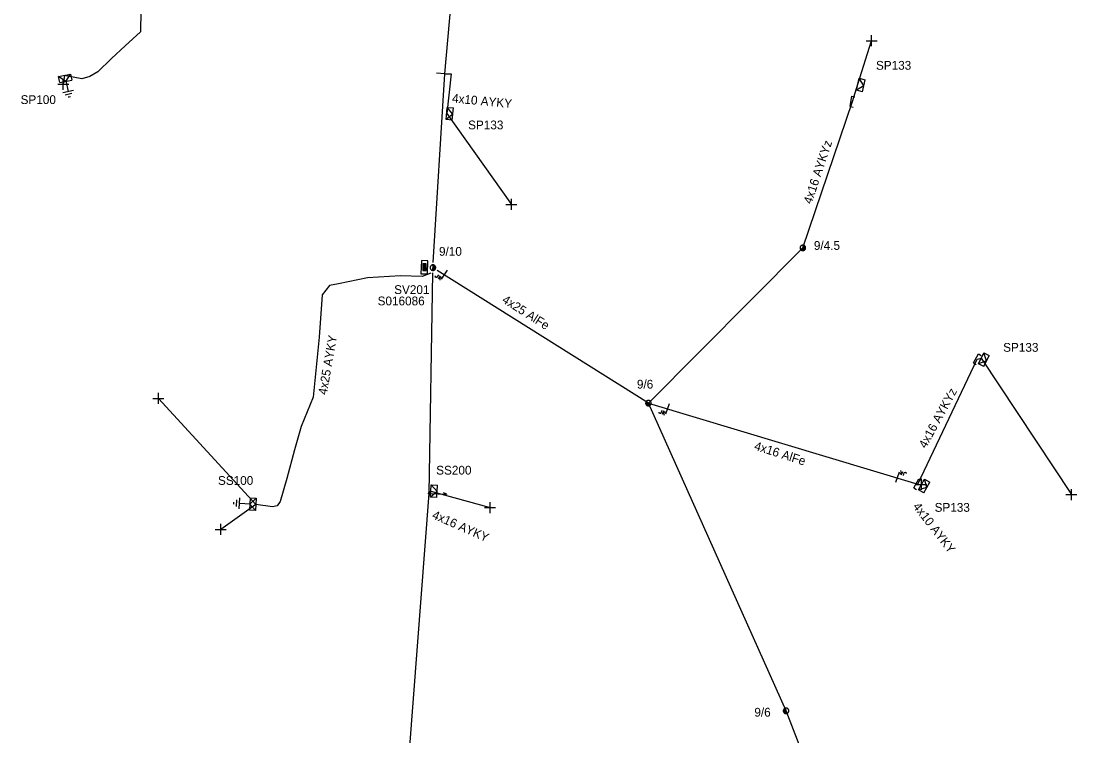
# Model space of a CAD drawing. Extents: x -717562 to -713845, y -1151196 to -1143903.
# Drawn here: x -717014.4 to -716894.3, y -1144985.4 to -1144904.2 of the extents above; entities that cross this region are included whole.
import ezdxf

# ---------------------------------------------------------------- set-up
doc = ezdxf.new("R2010")
doc.units = 0
for name, color, linetype in [('Vrstva 1', 7, 'Continuous'), ('Vrstva 12', 7, 'Continuous'), ('Vrstva 13', 7, 'Continuous'), ('Vrstva 14', 7, 'Continuous'), ('Vrstva 15', 7, 'Continuous'), ('Vrstva 18', 7, 'Continuous'), ('Vrstva 2', 7, 'Continuous'), ('Vrstva 28', 7, 'Continuous'), ('Vrstva 29', 7, 'Continuous'), ('Vrstva 30', 7, 'Continuous'), ('Vrstva 31', 7, 'Continuous'), ('Vrstva 33', 7, 'Continuous'), ('Vrstva 34', 7, 'Continuous'), ('Vrstva 52', 7, 'Continuous'), ('Vrstva 54', 7, 'Continuous'), ('Vrstva 55', 7, 'Continuous'), ('Vrstva 59', 7, 'Continuous'), ('Vrstva 8', 7, 'Continuous'), ('Vrstva 9', 7, 'Continuous')]:
    doc.layers.add(name, color=color, linetype=linetype)

# ---------------------------------------------------------------- blocks, each defined once
blk = doc.blocks.new('NN440')
at = {"layer": 'Vrstva 2'}
for points in [[(0.63, 0), (0.63, 0.06), (0.62, 0.13), (0.6, 0.19), (0.58, 0.25), (0.55, 0.31), (0.51, 0.37), (0.47, 0.42), (0.42, 0.46), (0.37, 0.51), (0.32, 0.54), (0.26, 0.57), (0.2, 0.59), (0.13, 0.61), (0.07, 0.62), (0, 0.63), (-0.06, 0.62), (-0.13, 0.61), (-0.19, 0.59), (-0.26, 0.57), (-0.31, 0.54), (-0.37, 0.51), (-0.42, 0.46), (-0.47, 0.42), (-0.51, 0.37), (-0.54, 0.31), (-0.57, 0.25), (-0.6, 0.19), (-0.62, 0.13), (-0.63, 0.06), (-0.63, 0), (-0.63, -0.07), (-0.62, -0.14), (-0.6, -0.2), (-0.57, -0.26), (-0.54, -0.32), (-0.51, -0.37), (-0.47, -0.43), (-0.42, -0.47), (-0.37, -0.51), (-0.31, -0.55), (-0.26, -0.58), (-0.19, -0.6), (-0.13, -0.62), (-0.06, -0.63), (0, -0.63), (0.07, -0.63), (0.13, -0.62), (0.2, -0.6), (0.26, -0.58), (0.32, -0.55), (0.37, -0.51), (0.42, -0.47), (0.47, -0.43), (0.51, -0.37), (0.55, -0.32), (0.58, -0.26), (0.6, -0.2), (0.62, -0.14), (0.63, -0.07), (0.63, 0)], [(-0.63, 0), (0.63, 0)], [(-0.6, -0.18), (0.57, -0.18)], [(-0.51, -0.32), (0.5, -0.32)], [(-0.37, -0.47), (0.35, -0.47)]]:
    blk.add_lwpolyline(points, dxfattribs=at)
blk = doc.blocks.new('NN560')
at = {"layer": 'Vrstva 2'}
for points in [[(2, 0), (1.59, 0.14)], [(0, 0), (2, 0)], [(2, 0), (1.59, -0.13)]]:
    blk.add_lwpolyline(points, dxfattribs=at)
blk = doc.blocks.new('NN840')
at = {"layer": 'Vrstva 15'}
for points in [[(0, 0.62), (0, -0.63)], [(-0.75, -0.71), (-0.75, -0.66)], [(-0.73, -0.76), (-0.75, -0.71)], [(-0.66, -0.8), (-0.73, -0.76)], [(-0.63, -0.8), (-0.66, -0.8)], [(-0.56, -0.76), (-0.63, -0.8)], [(-0.54, -0.71), (-0.56, -0.76)], [(-0.54, -0.38), (-0.54, -0.71)], [(-0.33, -0.38), (-0.33, -0.8)], [(-0.33, -0.64), (-0.13, -0.38)], [(-0.26, -0.56), (-0.09, -0.8)]]:
    blk.add_lwpolyline(points, dxfattribs=at)
blk = doc.blocks.new('NN800')
at = {"layer": 'Vrstva 1'}
for points in [[(-0.44, 0.44), (0.44, -0.44)], [(-0.44, -0.44), (0.44, 0.44)]]:
    blk.add_lwpolyline(points, dxfattribs=at)
blk = doc.blocks.new('NN620')
at = {"layer": 'Vrstva 8'}
for points in [[(0.75, 0), (-0.75, 0)], [(-0.75, 0), (-0.75, -0.75)], [(0.75, -0.75), (0.75, 0)], [(-0.75, -0.75), (0.75, -0.75)], [(0.37, -0.18), (-0.38, -0.18)], [(-0.38, -0.18), (-0.38, -0.56)], [(-0.38, -0.56), (0.37, -0.56)], [(0.32, -0.23), (-0.33, -0.23)], [(-0.33, -0.23), (-0.33, -0.51)], [(-0.33, -0.51), (0.32, -0.51)], [(0.27, -0.27), (-0.28, -0.27)], [(-0.28, -0.27), (-0.28, -0.46)], [(-0.28, -0.46), (0.27, -0.46)], [(0.23, -0.32), (-0.23, -0.32)], [(-0.23, -0.32), (-0.23, -0.42)], [(-0.23, -0.42), (0.23, -0.42)], [(-0.19, -0.37), (0.19, -0.37)], [(0.23, -0.42), (0.23, -0.32)], [(0.27, -0.46), (0.27, -0.27)], [(0.32, -0.51), (0.32, -0.23)], [(0.37, -0.56), (0.37, -0.18)]]:
    blk.add_lwpolyline(points, dxfattribs=at)
blk = doc.blocks.new('NN630')
at = {"layer": 'Vrstva 9'}
for points in [[(0, -0.7), (-0.7, 0)], [(-0.7, -0.7), (-0.7, 0), (0.7, 0), (0.7, -0.7)], [(-0.7, -0.7), (0.7, -0.7)], [(0, -0.7), (0.7, 0)]]:
    blk.add_lwpolyline(points, dxfattribs=at)
blk = doc.blocks.new('NN810')
at = {"layer": 'Vrstva 14'}
for points in [[(0, -0.64), (0, -1.89)], [(0.63, -1.89), (-0.62, -1.89)], [(0.39, -2.2), (-0.4, -2.2)], [(0, -2.52), (-0.12, -2.52)], [(0.14, -2.52), (0, -2.52)]]:
    blk.add_lwpolyline(points, dxfattribs=at)
blk = doc.blocks.new('NN500')
at = {"layer": 'Vrstva 2'}
for points in [[(0, -0.24), (0.02, -0.23), (0.05, -0.23), (0.07, -0.22), (0.09, -0.22), (0.12, -0.2), (0.14, -0.19), (0.16, -0.18), (0.17, -0.16), (0.19, -0.14), (0.2, -0.12), (0.21, -0.1), (0.22, -0.07), (0.23, -0.05), (0.23, -0.02), (0.23, 0), (0.23, 0.02), (0.23, 0.05), (0.22, 0.07), (0.21, 0.1), (0.2, 0.12), (0.19, 0.14), (0.17, 0.16), (0.16, 0.17), (0.14, 0.19), (0.12, 0.2), (0.09, 0.21), (0.07, 0.22), (0.05, 0.23), (0.02, 0.23), (0, 0.23), (-0.03, 0.23), (-0.05, 0.23), (-0.07, 0.22), (-0.1, 0.21), (-0.12, 0.2), (-0.14, 0.19), (-0.16, 0.17), (-0.18, 0.16), (-0.19, 0.14), (-0.2, 0.12), (-0.22, 0.1), (-0.22, 0.07), (-0.23, 0.05), (-0.23, 0.02), (-0.24, 0), (-0.23, -0.02), (-0.23, -0.05), (-0.22, -0.07), (-0.22, -0.1), (-0.2, -0.12), (-0.19, -0.14), (-0.18, -0.16), (-0.16, -0.18), (-0.14, -0.19), (-0.12, -0.2), (-0.1, -0.22), (-0.07, -0.22), (-0.05, -0.23), (-0.03, -0.23), (0, -0.24)], [(0, -0.24), (0.02, -0.23), (0.05, -0.23), (0.07, -0.22), (0.09, -0.22), (0.12, -0.2), (0.14, -0.19), (0.16, -0.18), (0.17, -0.16), (0.19, -0.14), (0.2, -0.12), (0.21, -0.1), (0.22, -0.07), (0.23, -0.05), (0.23, -0.02), (0.23, 0), (0.23, 0.02), (0.23, 0.05), (0.22, 0.07), (0.21, 0.1), (0.2, 0.12), (0.19, 0.14), (0.17, 0.16), (0.16, 0.17), (0.14, 0.19), (0.12, 0.2), (0.09, 0.21), (0.07, 0.22), (0.05, 0.23), (0.02, 0.23), (0, 0.23), (-0.03, 0.23), (-0.05, 0.23), (-0.07, 0.22), (-0.1, 0.21), (-0.12, 0.2), (-0.14, 0.19), (-0.16, 0.17), (-0.18, 0.16), (-0.19, 0.14), (-0.2, 0.12), (-0.22, 0.1), (-0.22, 0.07), (-0.23, 0.05), (-0.23, 0.02), (-0.24, 0), (-0.23, -0.02), (-0.23, -0.05), (-0.22, -0.07), (-0.22, -0.1), (-0.2, -0.12), (-0.19, -0.14), (-0.18, -0.16), (-0.16, -0.18), (-0.14, -0.19), (-0.12, -0.2), (-0.1, -0.22), (-0.07, -0.22), (-0.05, -0.23), (-0.03, -0.23), (0, -0.24)], [(0, -0.21), (0.02, -0.2), (0.04, -0.2), (0.06, -0.2), (0.08, -0.19), (0.1, -0.18), (0.12, -0.17), (0.14, -0.15), (0.15, -0.14), (0.16, -0.12), (0.18, -0.1), (0.19, -0.08), (0.19, -0.06), (0.2, -0.04), (0.2, -0.02), (0.2, 0), (0.2, 0.02), (0.2, 0.04), (0.19, 0.06), (0.19, 0.08), (0.18, 0.1), (0.16, 0.12), (0.15, 0.14), (0.14, 0.15), (0.12, 0.17), (0.1, 0.18), (0.08, 0.19), (0.06, 0.19), (0.04, 0.2), (0.02, 0.2), (0, 0.2), (-0.02, 0.2), (-0.04, 0.2), (-0.06, 0.19), (-0.08, 0.19), (-0.1, 0.18), (-0.12, 0.17), (-0.14, 0.15), (-0.15, 0.14), (-0.17, 0.12), (-0.18, 0.1), (-0.19, 0.08), (-0.2, 0.06), (-0.2, 0.04), (-0.21, 0.02), (-0.21, 0), (-0.21, -0.02), (-0.2, -0.04), (-0.2, -0.06), (-0.19, -0.08), (-0.18, -0.1), (-0.17, -0.12), (-0.15, -0.14), (-0.14, -0.15), (-0.12, -0.17), (-0.1, -0.18), (-0.08, -0.19), (-0.06, -0.2), (-0.04, -0.2), (-0.02, -0.2), (0, -0.21)], [(0, -0.18), (0.02, -0.18), (0.04, -0.17), (0.05, -0.17), (0.07, -0.16), (0.09, -0.15), (0.1, -0.14), (0.12, -0.13), (0.13, -0.12), (0.14, -0.1), (0.15, -0.09), (0.16, -0.07), (0.17, -0.05), (0.17, -0.04), (0.17, -0.02), (0.17, 0), (0.17, 0.02), (0.17, 0.04), (0.17, 0.05), (0.16, 0.07), (0.15, 0.09), (0.14, 0.1), (0.13, 0.12), (0.12, 0.13), (0.1, 0.14), (0.09, 0.15), (0.07, 0.16), (0.05, 0.17), (0.04, 0.17), (0.02, 0.17), (0, 0.18), (-0.02, 0.17), (-0.04, 0.17), (-0.06, 0.17), (-0.07, 0.16), (-0.09, 0.15), (-0.1, 0.14), (-0.12, 0.13), (-0.13, 0.12), (-0.14, 0.1), (-0.15, 0.09), (-0.16, 0.07), (-0.17, 0.05), (-0.17, 0.04), (-0.18, 0.02), (-0.18, 0), (-0.18, -0.02), (-0.17, -0.04), (-0.17, -0.05), (-0.16, -0.07), (-0.15, -0.09), (-0.14, -0.1), (-0.13, -0.12), (-0.12, -0.13), (-0.1, -0.14), (-0.09, -0.15), (-0.07, -0.16), (-0.06, -0.17), (-0.04, -0.17), (-0.02, -0.18), (0, -0.18)], [(0, -0.15), (0.01, -0.15), (0.03, -0.14), (0.04, -0.14), (0.06, -0.13), (0.07, -0.13), (0.08, -0.12), (0.1, -0.11), (0.11, -0.1), (0.12, -0.09), (0.13, -0.07), (0.13, -0.06), (0.14, -0.05), (0.14, -0.03), (0.14, -0.02), (0.14, 0), (0.14, 0.01), (0.14, 0.03), (0.14, 0.04), (0.13, 0.06), (0.13, 0.07), (0.12, 0.09), (0.11, 0.1), (0.1, 0.11), (0.08, 0.12), (0.07, 0.13), (0.06, 0.13), (0.04, 0.14), (0.03, 0.14), (0.01, 0.14), (0, 0.15), (-0.02, 0.14), (-0.03, 0.14), (-0.05, 0.14), (-0.06, 0.13), (-0.07, 0.13), (-0.09, 0.12), (-0.1, 0.11), (-0.11, 0.1), (-0.12, 0.09), (-0.13, 0.07), (-0.13, 0.06), (-0.14, 0.04), (-0.14, 0.03), (-0.15, 0.01), (-0.15, 0), (-0.15, -0.02), (-0.14, -0.03), (-0.14, -0.05), (-0.13, -0.06), (-0.13, -0.07), (-0.12, -0.09), (-0.11, -0.1), (-0.1, -0.11), (-0.09, -0.12), (-0.07, -0.13), (-0.06, -0.13), (-0.05, -0.14), (-0.03, -0.14), (-0.02, -0.15), (0, -0.15)], [(0, -0.12), (0.01, -0.12), (0.02, -0.11), (0.03, -0.11), (0.05, -0.11), (0.06, -0.1), (0.07, -0.09), (0.08, -0.09), (0.09, -0.08), (0.09, -0.07), (0.1, -0.06), (0.11, -0.05), (0.11, -0.04), (0.11, -0.02), (0.11, -0.01), (0.12, 0), (0.11, 0.01), (0.11, 0.02), (0.11, 0.04), (0.11, 0.05), (0.1, 0.06), (0.09, 0.07), (0.09, 0.08), (0.08, 0.09), (0.07, 0.09), (0.06, 0.1), (0.05, 0.11), (0.03, 0.11), (0.02, 0.11), (0.01, 0.12), (0, 0.12), (-0.01, 0.12), (-0.03, 0.11), (-0.04, 0.11), (-0.05, 0.11), (-0.06, 0.1), (-0.07, 0.09), (-0.08, 0.09), (-0.09, 0.08), (-0.1, 0.07), (-0.1, 0.06), (-0.11, 0.05), (-0.11, 0.04), (-0.12, 0.02), (-0.12, 0.01), (-0.12, 0), (-0.12, -0.01), (-0.12, -0.02), (-0.11, -0.04), (-0.11, -0.05), (-0.1, -0.06), (-0.1, -0.07), (-0.09, -0.08), (-0.08, -0.09), (-0.07, -0.09), (-0.06, -0.1), (-0.05, -0.11), (-0.04, -0.11), (-0.03, -0.11), (-0.01, -0.12), (0, -0.12)], [(0, -0.09), (0.01, -0.09), (0.02, -0.09), (0.03, -0.08), (0.03, -0.08), (0.04, -0.08), (0.05, -0.07), (0.06, -0.07), (0.06, -0.06), (0.07, -0.05), (0.07, -0.04), (0.08, -0.04), (0.08, -0.03), (0.08, -0.02), (0.09, -0.01), (0.09, 0), (0.09, 0.01), (0.08, 0.02), (0.08, 0.03), (0.08, 0.03), (0.07, 0.04), (0.07, 0.05), (0.06, 0.06), (0.06, 0.06), (0.05, 0.07), (0.04, 0.07), (0.03, 0.08), (0.03, 0.08), (0.02, 0.08), (0.01, 0.09), (0, 0.09), (-0.01, 0.09), (-0.02, 0.08), (-0.03, 0.08), (-0.04, 0.08), (-0.04, 0.07), (-0.05, 0.07), (-0.06, 0.06), (-0.07, 0.06), (-0.07, 0.05), (-0.08, 0.04), (-0.08, 0.03), (-0.08, 0.03), (-0.09, 0.02), (-0.09, 0.01), (-0.09, 0), (-0.09, -0.01), (-0.09, -0.02), (-0.08, -0.03), (-0.08, -0.04), (-0.08, -0.04), (-0.07, -0.05), (-0.07, -0.06), (-0.06, -0.07), (-0.05, -0.07), (-0.04, -0.08), (-0.04, -0.08), (-0.03, -0.08), (-0.02, -0.09), (-0.01, -0.09), (0, -0.09)], [(0, -0.06), (0, -0.06), (0.01, -0.06), (0.02, -0.05), (0.02, -0.05), (0.03, -0.05), (0.03, -0.05), (0.04, -0.04), (0.04, -0.04), (0.05, -0.03), (0.05, -0.03), (0.05, -0.02), (0.05, -0.02), (0.05, -0.01), (0.06, -0.01), (0.06, 0), (0.06, 0.01), (0.05, 0.01), (0.05, 0.02), (0.05, 0.02), (0.05, 0.03), (0.05, 0.03), (0.04, 0.04), (0.04, 0.04), (0.03, 0.05), (0.03, 0.05), (0.02, 0.05), (0.02, 0.05), (0.01, 0.06), (0, 0.06), (0, 0.06), (-0.01, 0.06), (-0.01, 0.06), (-0.02, 0.05), (-0.02, 0.05), (-0.03, 0.05), (-0.03, 0.05), (-0.04, 0.04), (-0.04, 0.04), (-0.05, 0.03), (-0.05, 0.03), (-0.05, 0.02), (-0.06, 0.02), (-0.06, 0.01), (-0.06, 0.01), (-0.06, 0), (-0.06, -0.01), (-0.06, -0.01), (-0.06, -0.02), (-0.05, -0.02), (-0.05, -0.03), (-0.05, -0.03), (-0.04, -0.04), (-0.04, -0.04), (-0.03, -0.05), (-0.03, -0.05), (-0.02, -0.05), (-0.02, -0.05), (-0.01, -0.06), (-0.01, -0.06), (0, -0.06)], [(0, -0.03), (0, -0.03), (0, -0.03), (0.01, -0.03), (0.01, -0.03), (0.01, -0.02), (0.02, -0.02), (0.02, -0.02), (0.02, -0.02), (0.02, -0.02), (0.02, -0.01), (0.02, -0.01), (0.03, -0.01), (0.03, -0.01), (0.03, 0), (0.03, 0), (0.03, 0), (0.03, 0.01), (0.03, 0.01), (0.02, 0.01), (0.02, 0.01), (0.02, 0.02), (0.02, 0.02), (0.02, 0.02), (0.02, 0.02), (0.01, 0.02), (0.01, 0.02), (0.01, 0.03), (0, 0.03), (0, 0.03), (0, 0.03), (0, 0.03), (-0.01, 0.03), (-0.01, 0.03), (-0.01, 0.02), (-0.02, 0.02), (-0.02, 0.02), (-0.02, 0.02), (-0.02, 0.02), (-0.02, 0.02), (-0.03, 0.01), (-0.03, 0.01), (-0.03, 0.01), (-0.03, 0.01), (-0.03, 0), (-0.03, 0), (-0.03, 0), (-0.03, -0.01), (-0.03, -0.01), (-0.03, -0.01), (-0.03, -0.01), (-0.02, -0.02), (-0.02, -0.02), (-0.02, -0.02), (-0.02, -0.02), (-0.02, -0.02), (-0.01, -0.03), (-0.01, -0.03), (-0.01, -0.03), (0, -0.03), (0, -0.03)], [(0.23, 0), (0.7, 0)]]:
    blk.add_lwpolyline(points, dxfattribs=at)
blk = doc.blocks.new('NN510')
at = {"layer": 'Vrstva 2'}
blk.add_lwpolyline([(0, 0), (0, 0.94)], dxfattribs=at)
blk = doc.blocks.new('NN515')
at = {"layer": 'Vrstva 2'}
for points in [[(-0.59, 0.18), (0.59, 0.18)], [(-0.59, 0.18), (-0.59, -0.18)], [(0.59, 0.18), (0.59, -0.18)]]:
    blk.add_lwpolyline(points, dxfattribs=at)

msp = doc.modelspace()

# ---------------------------------------------------------------- linework, layer by layer
at = {"layer": 'Vrstva 1'}
for points in [[(-716967.53, -1144931.61), (-716966.2, -1144910.14), (-716963.5, -1144879.93), (-716959.89, -1144843.56)], [(-716976.49, -1145065.91), (-716974.89, -1145052.28), (-716974.23, -1145033.61), (-716971.11, -1144998.55), (-716967.97, -1144957.87), (-716967.57, -1144932.78)], [(-716943.05, -1144947.6), (-716967.06, -1144932.5)], [(-716913.64, -1145018.13), (-716927.39, -1144982.6), (-716943.05, -1144947.6)], [(-716943.05, -1144947.6), (-716912.41, -1144956.82)]]:
    msp.add_lwpolyline(points, dxfattribs=at)
at = {"layer": 'Vrstva 52'}
for points in [[(-716974.29, -1144834.64), (-716974.85, -1144834.87), (-716979.71, -1144835.48), (-716983.86, -1144836.02), (-716984.57, -1144837.52), (-716985.63, -1144846.66), (-716985.88, -1144861.33), (-716987.12, -1144880.09), (-716989.7, -1144883.35), (-716991.01, -1144885.73), (-716993.14, -1144889.16), (-716996.41, -1144892.78), (-716999.13, -1144896.11), (-717000.21, -1144897.91), (-717000.51, -1144898.92), (-717000.75, -1144900.59), (-717000.84, -1144905.38), (-717002.58, -1144906.97), (-717004.13, -1144908.42), (-717005.67, -1144909.9), (-717006.59, -1144910.44), (-717007.51, -1144910.72), (-717009.45, -1144910.32)], [(-716966.2, -1144910.14), (-716965.49, -1144910.15), (-716965.99, -1144914.66)], [(-716967.79, -1144932.83), (-716968.78, -1144933.18), (-716971.23, -1144933.13), (-716974.99, -1144933.36), (-716978.3, -1144934.04), (-716979.34, -1144934.22), (-716980.14, -1144935.28), (-716980.51, -1144940.11), (-716981.18, -1144946.91), (-716982.53, -1144950.27), (-716983.31, -1144952.91), (-716984.18, -1144956.17), (-716984.94, -1144958.8), (-716985.29, -1144959.27), (-716985.81, -1144959.38), (-716987.69, -1144959.12)], [(-716912.41, -1144956.82), (-716911.99, -1144956.85)], [(-716967.97, -1144957.87), (-716967.79, -1144957.6)]]:
    msp.add_lwpolyline(points, dxfattribs=at)
at = {"layer": 'Vrstva 54'}
for points in [[(-716943.05, -1144947.6), (-716925.49, -1144929.94), (-716919.83, -1144913.31), (-716919.23, -1144911.33)], [(-716912.41, -1144956.82), (-716905.64, -1144942.61), (-716905.21, -1144942.5)]]:
    msp.add_lwpolyline(points, dxfattribs=at)
at = {"layer": 'Vrstva 59'}
for points in [[(-716919.23, -1144911.33), (-716917.66, -1144906.38)], [(-717009.45, -1144910.32), (-717009.6, -1144911.33)], [(-716965.99, -1144914.66), (-716958.63, -1144925)], [(-716905.21, -1144942.5), (-716894.94, -1144958)], [(-716987.69, -1144959.12), (-716998.79, -1144947.07)], [(-716967.79, -1144957.6), (-716961.06, -1144959.48)], [(-716987.69, -1144959.12), (-716991.69, -1144961.97)]]:
    msp.add_lwpolyline(points, dxfattribs=at)

# ---------------------------------------------------------------- block references
at = {"layer": 'Vrstva 13'}
for name, p, rotation in [('NN510', (-716966.2, -1144910.14), 84.89279440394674), ('NN515', (-716919.83, -1144913.31), 81.14871944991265), ('NN515', (-716905.64, -1144942.61), 60.69199165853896), ('NN515', (-716912.41, -1144956.82), 60.69199165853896), ('NN560', (-716967.97, -1144957.87), -2.846106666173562)]:
    msp.add_blockref(name, p, dxfattribs=dict(at, rotation=rotation))
for name, p, xscale, yscale, rotation in [('NN440', (-716925.49, -1144929.94), 0.49999999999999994, 0.5000000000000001, 35.69115279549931), ('NN440', (-716967.56, -1144932.19), 0.5, 0.5, 84.83481945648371), ('NN440', (-716943.05, -1144947.6), 0.5, 0.5, -32.90626104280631), ('NN500', (-716967.97, -1144957.87), 0.5, 0.5, 90), ('NN440', (-716927.39, -1144982.6), 0.5, 0.5, -72.36235830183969)]:
    msp.add_blockref(name, p, dxfattribs=dict(at, xscale=xscale, yscale=yscale, rotation=rotation))
at = {"layer": 'Vrstva 15'}
for p, rotation in [((-717009.45, -1144910.32), 11.73081671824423), ((-716987.69, -1144959.12), -93.47672777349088)]:
    msp.add_blockref('NN810', p, dxfattribs=dict(at, rotation=rotation))
at = {"layer": 'Vrstva 18'}
for p, rotation in [((-716966.27, -1144932.98), -32.90626100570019), ((-716940.89, -1144948.25), -19.79997775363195), ((-716914.69, -1144956), 160.20002224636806)]:
    msp.add_blockref('NN840', p, dxfattribs=dict(at, rotation=rotation))
at = {"layer": 'Vrstva 28', "rotation": -91.59800000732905}
msp.add_blockref('NN620', (-716968.15, -1144932.15), dxfattribs=at)
at = {"layer": 'Vrstva 31'}
for p, rotation in [((-717009.45, -1144910.32), 11.73081671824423), ((-716919.23, -1144911.33), 76.13929416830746), ((-716965.99, -1144914.66), 84.58205003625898), ((-716905.21, -1144942.5), 64.43812764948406), ((-716911.99, -1144956.85), 60.69199165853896), ((-716967.79, -1144957.6), 87.13710281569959), ((-716987.69, -1144959.12), -93.47672777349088)]:
    msp.add_blockref('NN630', p, dxfattribs=dict(at, rotation=rotation))
at = {"layer": 'Vrstva 34'}
for p, rotation in [((-716917.66, -1144906.38), 45), ((-717009.6, -1144911.33), 45), ((-716958.63, -1144925), 45), ((-716998.79, -1144947.07), 45), ((-716911.99, -1144956.85), 45), ((-716894.94, -1144958), 44.99999995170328), ((-716961.06, -1144959.48), 45), ((-716991.69, -1144961.97), 45)]:
    msp.add_blockref('NN800', p, dxfattribs=dict(at, rotation=rotation))

# ---------------------------------------------------------------- texts
at = {"layer": 'Vrstva 12'}
for s, p in [('9/4.5', (-716924.23, -1144930.17)), ('9/10', (-716966.87, -1144930.84)), ('9/6', (-716944.36, -1144945.95)), ('9/6', (-716931, -1144983.26))]:
    msp.add_text(s, height=1, dxfattribs=at).set_placement(p)
at = {"layer": 'Vrstva 2'}
for s, rotation, p in [('4x25 AlFe', 327.491, (-716959.79, -1144936.08)), ('4x16 AlFe', 342.317, (-716931.09, -1144952.88))]:
    msp.add_text(s, height=1, rotation=rotation, dxfattribs=at).set_placement(p)
at = {"layer": 'Vrstva 29'}
msp.add_text('S016086', height=1, dxfattribs=at).set_placement((-716973.85, -1144936.48))
at = {"layer": 'Vrstva 30'}
msp.add_text('SV201', height=1, dxfattribs=at).set_placement((-716971.97, -1144935.19))
at = {"layer": 'Vrstva 33'}
for s, p in [('SP133', (-716917.17, -1144909.68)), ('SP100', (-717014.46, -1144913.58)), ('SP133', (-716963.56, -1144916.46)), ('SP133', (-716902.7, -1144941.76)), ('SS200', (-716967.19, -1144955.73)), ('SS100', (-716992.01, -1144956.9)), ('SP133', (-716910.5, -1144959.96))]:
    msp.add_text(s, height=1, dxfattribs=at).set_placement(p)
at = {"layer": 'Vrstva 54'}
for s, rotation, p in [('4x10 AYKY', 354.582, (-716965.42, -1144913.4)), ('4x25 AYKY', 80.057, (-716979.64, -1144946.71)), ('4x10 AYKY', 307.691, (-716913.03, -1144959.37)), ('4x16 AYKY', 336.278, (-716967.74, -1144960.67))]:
    msp.add_text(s, height=1, rotation=rotation, dxfattribs=at).set_placement(p)
at = {"layer": 'Vrstva 55'}
for rotation, p in [(71.617, (-716924.5, -1144925.03)), (61.557, (-716911.49, -1144952.83))]:
    msp.add_text('4x16 AYKYz', height=1, rotation=rotation, dxfattribs=at).set_placement(p)

doc.saveas('drawing.dxf')
